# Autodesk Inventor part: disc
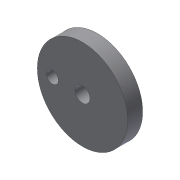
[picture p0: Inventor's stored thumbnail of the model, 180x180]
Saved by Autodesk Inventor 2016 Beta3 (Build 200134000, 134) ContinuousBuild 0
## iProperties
Created: 2016-03
Part Number: disc
Material: Generic
Document SubType Name: Modeling
Designer: Gaurav
Density: 1 g/cm^3
Appearance: Default
Author: Gaurav
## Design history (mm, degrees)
sketch "Sketch1"
  geometry: C1 r 15 at (0, 0); C2 r 2.5 at (0, 0); C3 r 2 at (10, 0); 1 further point
  constraints: 3 centre point, 2 coincident
  dimensions: "d0" = 30 diameter of C1; "d1" = 5 diameter of C2; "d2" = 4 diameter of C3; "d3" = 10 distance of point (0, 0) C3.centre
extrude "Extrusion1" new body sketch "Sketch1" distance "d4" = 5; taper "d5" = 0 deg
body "Solid1"
